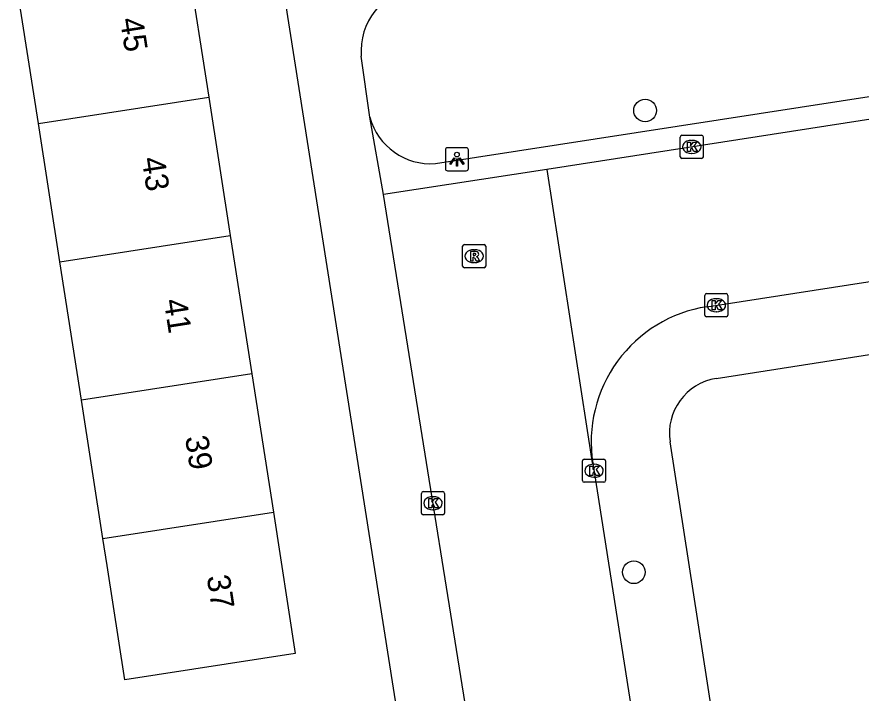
# Model space of a CAD drawing. Extents: x 160077 to 160945, y 386481 to 387498.
# Drawn here: x 160327.89 to 160364.4, y 387381.1 to 387410.32 of the extents above; entities that cross this region are included whole.
import ezdxf

# ---------------------------------------------------------------- set-up
doc = ezdxf.new("R2010")
doc.units = 0
for name, color, linetype in [('IMGEO_Boom', 7, 'Continuous'), ('IMGEO_Kolk', 7, 'Continuous'), ('IMGEO_Lichtpunt', 7, 'Continuous'), ('IMGEO_Pand', 7, 'Continuous'), ('IMGEO_Pand_nummerreeks', 7, 'Continuous'), ('IMGEO_Rijbaan_lokaal_open', 7, 'Continuous'), ('IMGEO_Rioolput', 7, 'Continuous'), ('IMGEO_Voetpad_open', 7, 'Continuous')]:
    doc.layers.add(name, color=color, linetype=linetype)

msp = doc.modelspace()

# ---------------------------------------------------------------- linework, layer by layer
at = {"layer": 'IMGEO_Boom'}
for centre in [(160355.058, 387406.272), (160354.57, 387386.318)]:
    msp.add_circle(centre, 0.489, dxfattribs=at)
at = {"layer": 'IMGEO_Kolk'}
for p, q in [((160356.576, 387404.276), (160356.576, 387405.128)), ((160356.651, 387405.202), (160357.503, 387405.202)), ((160357.577, 387405.128), (160357.577, 387404.276)), ((160357.064, 387404.982), (160357.089, 387404.982)), ((160357.087, 387404.422), (160357.062, 387404.422)), ((160357.503, 387404.202), (160356.651, 387404.202)), ((160357.64, 387397.432), (160357.64, 387398.284)), ((160357.715, 387398.358), (160358.567, 387398.358)), ((160358.641, 387398.284), (160358.641, 387397.432)), ((160358.128, 387398.138), (160358.153, 387398.138)), ((160358.151, 387397.578), (160358.126, 387397.578)), ((160358.567, 387397.358), (160357.715, 387397.358)), ((160352.35, 387390.279), (160352.35, 387391.131)), ((160352.425, 387391.205), (160353.277, 387391.205)), ((160352.838, 387390.985), (160352.863, 387390.985)), ((160353.351, 387391.131), (160353.351, 387390.279)), ((160353.277, 387390.205), (160352.425, 387390.205)), ((160352.861, 387390.425), (160352.836, 387390.425)), ((160345.463, 387389.801), (160346.315, 387389.801)), ((160345.388, 387388.875), (160345.388, 387389.727)), ((160345.876, 387389.581), (160345.901, 387389.581)), ((160346.389, 387389.727), (160346.389, 387388.875)), ((160346.315, 387388.801), (160345.463, 387388.801)), ((160345.899, 387389.021), (160345.874, 387389.021))]:
    msp.add_line(p, q, dxfattribs=at)
for points in [[(160356.576, 387404.276), (160356.576, 387405.128)], [(160356.651, 387405.202), (160357.503, 387405.202)], [(160357.577, 387405.128), (160357.577, 387404.276)], [(160356.897, 387404.902), (160357.02, 387404.902), (160357.02, 387404.751), (160357.15, 387404.902), (160357.314, 387404.902), (160357.168, 387404.751), (160357.321, 387404.502), (160357.169, 387404.502), (160357.084, 387404.666), (160357.02, 387404.599), (160357.02, 387404.502), (160356.897, 387404.502), (160356.897, 387404.902)], [(160357.503, 387404.202), (160356.651, 387404.202)], [(160357.64, 387397.432), (160357.64, 387398.284)], [(160357.715, 387398.358), (160358.567, 387398.358)], [(160358.641, 387398.284), (160358.641, 387397.432)], [(160357.961, 387398.058), (160358.084, 387398.058), (160358.084, 387397.907), (160358.214, 387398.058), (160358.378, 387398.058), (160358.232, 387397.907), (160358.385, 387397.658), (160358.233, 387397.658), (160358.148, 387397.822), (160358.084, 387397.755), (160358.084, 387397.658), (160357.961, 387397.658), (160357.961, 387398.058)], [(160358.567, 387397.358), (160357.715, 387397.358)], [(160352.35, 387390.279), (160352.35, 387391.131)], [(160352.425, 387391.205), (160353.277, 387391.205)], [(160352.671, 387390.905), (160352.794, 387390.905), (160352.794, 387390.754), (160352.924, 387390.905), (160353.088, 387390.905), (160352.942, 387390.754), (160353.095, 387390.505), (160352.943, 387390.505), (160352.858, 387390.669), (160352.794, 387390.602), (160352.794, 387390.505), (160352.671, 387390.505), (160352.671, 387390.905)], [(160353.351, 387391.131), (160353.351, 387390.279)], [(160353.277, 387390.205), (160352.425, 387390.205)], [(160345.463, 387389.801), (160346.315, 387389.801)], [(160345.388, 387388.875), (160345.388, 387389.727)], [(160345.709, 387389.501), (160345.832, 387389.501), (160345.832, 387389.35), (160345.962, 387389.501), (160346.126, 387389.501), (160345.98, 387389.35), (160346.133, 387389.101), (160345.981, 387389.101), (160345.896, 387389.265), (160345.832, 387389.198), (160345.832, 387389.101), (160345.709, 387389.101), (160345.709, 387389.501)], [(160346.389, 387389.727), (160346.389, 387388.875)], [(160346.315, 387388.801), (160345.463, 387388.801)]]:
    msp.add_lwpolyline(points, dxfattribs=at)
for centre, start, end in [((160356.653, 387405.126), 91.552, 178.448), ((160356.653, 387405.126), 91.552, 178.448), ((160357.501, 387405.126), 1.552, 88.448), ((160357.501, 387405.126), 1.552, 88.448), ((160356.653, 387404.278), 181.552, 268.448), ((160356.653, 387404.278), 181.552, 268.448), ((160357.501, 387404.278), 271.552, 358.448), ((160357.501, 387404.278), 271.552, 358.448), ((160357.717, 387398.282), 91.552, 178.448), ((160357.717, 387398.282), 91.552, 178.448), ((160358.565, 387398.282), 1.552, 88.448), ((160358.565, 387398.282), 1.552, 88.448), ((160357.717, 387397.434), 181.552, 268.448), ((160357.717, 387397.434), 181.552, 268.448), ((160358.565, 387397.434), 271.552, 358.448), ((160358.565, 387397.434), 271.552, 358.448), ((160352.427, 387391.129), 91.552, 178.448), ((160352.427, 387391.129), 91.552, 178.448), ((160353.275, 387391.129), 1.552, 88.448), ((160353.275, 387391.129), 1.552, 88.448), ((160352.427, 387390.281), 181.552, 268.448), ((160352.427, 387390.281), 181.552, 268.448), ((160353.275, 387390.281), 271.552, 358.448), ((160353.275, 387390.281), 271.552, 358.448), ((160345.465, 387389.725), 91.552, 178.448), ((160345.465, 387389.725), 91.552, 178.448), ((160346.313, 387389.725), 1.552, 88.448), ((160346.313, 387389.725), 1.552, 88.448), ((160345.465, 387388.877), 181.552, 268.448), ((160345.465, 387388.877), 181.552, 268.448), ((160346.313, 387388.877), 271.552, 358.448), ((160346.313, 387388.877), 271.552, 358.448)]:
    msp.add_arc(centre, 0.0765, start, end, dxfattribs=at)
for centre, major_axis, ratio, start_param, end_param in [((160357.063, 387404.702), (-0.387, 0.002), 0.722429, 4.712389, 7.853982), ((160357.088, 387404.702), (-0.39, 0.002), 0.717154, 1.570796, 4.712389), ((160358.127, 387397.858), (-0.387, 0.002), 0.722429, 4.712389, 7.853982), ((160358.152, 387397.858), (-0.39, 0.002), 0.717154, 1.570796, 4.712389), ((160352.837, 387390.705), (-0.387, 0.002), 0.722429, 4.712389, 7.853982), ((160352.862, 387390.705), (-0.39, 0.002), 0.717154, 1.570796, 4.712389), ((160345.875, 387389.301), (-0.387, 0.002), 0.722429, 4.712389, 7.853982), ((160345.9, 387389.301), (-0.39, 0.002), 0.717154, 1.570796, 4.712389)]:
    msp.add_ellipse(centre, major_axis=major_axis, ratio=ratio, start_param=start_param, end_param=end_param, dxfattribs=at)
at = {"layer": 'IMGEO_Lichtpunt'}
for p, q in [((160346.422, 387404.571), (160346.422, 387403.764)), ((160346.422, 387404.571), (160346.422, 387403.764)), ((160347.324, 387404.666), (160346.516, 387404.666)), ((160347.324, 387404.666), (160346.516, 387404.666)), ((160347.418, 387403.764), (160347.418, 387404.571)), ((160347.418, 387403.764), (160347.418, 387404.571)), ((160346.516, 387403.67), (160347.324, 387403.67)), ((160346.516, 387403.67), (160347.324, 387403.67))]:
    msp.add_line(p, q, dxfattribs=at)
for points in [[(160346.796, 387404.235), (160346.835, 387404.207), (160346.647, 387403.945), (160346.609, 387403.972), (160346.796, 387404.235)], [(160346.898, 387404.187), (160346.945, 387404.187), (160346.945, 387403.865), (160346.898, 387403.865), (160346.898, 387404.187)], [(160347.008, 387404.207), (160347.046, 387404.234), (160347.233, 387403.972), (160347.194, 387403.944), (160347.008, 387404.207)]]:
    msp.add_lwpolyline(points, dxfattribs=at)
msp.add_circle((160346.921, 387404.369), 0.0994, dxfattribs=at)
for centre, start, end in [((160346.516, 387404.571), 90, 180), ((160346.516, 387404.571), 90, 180), ((160347.324, 387404.571), 0, 90), ((160347.324, 387404.571), 0, 90), ((160346.516, 387403.764), 180, 270), ((160346.516, 387403.764), 180, 270), ((160347.324, 387403.764), 270, 0), ((160347.324, 387403.764), 270, 360)]:
    msp.add_arc(centre, 0.0946, start, end, dxfattribs=at)
at = {"layer": 'IMGEO_Pand'}
for points in [[(160335.263, 387412.83), (160336.194, 387406.852)], [(160328.826, 387405.705), (160327.895, 387411.683)], [(160328.826, 387405.705), (160336.194, 387406.852)], [(160336.194, 387406.852), (160337.124, 387400.875)], [(160329.756, 387399.728), (160328.826, 387405.705)], [(160329.756, 387399.728), (160337.124, 387400.875)], [(160337.124, 387400.875), (160338.054, 387394.897)], [(160330.686, 387393.75), (160329.756, 387399.728)], [(160338.054, 387394.897), (160330.686, 387393.75)], [(160338.054, 387394.897), (160338.984, 387388.919)], [(160331.616, 387387.772), (160330.686, 387393.75)], [(160338.984, 387388.919), (160339.935, 387382.811), (160332.567, 387381.664), (160331.798, 387386.605), (160331.616, 387387.772)], [(160331.616, 387387.772), (160338.984, 387388.919)]]:
    msp.add_lwpolyline(points, dxfattribs=at)
at = {"layer": 'IMGEO_Rijbaan_lokaal_open'}
for points in [[(160424.814, 387415.201), (160415.588, 387413.774), (160377.259, 387407.826), (160350.809, 387403.731)], [(160357.735, 387397.796), (160404.969, 387405.121), (160426.161, 387408.269)], [(160350.809, 387403.731), (160343.75, 387402.638)], [(160350.809, 387403.731), (160352.774, 387391.05), (160352.799, 387391.033)], [(160348.577, 387372.565), (160343.75, 387402.638)], [(160352.799, 387391.033), (160358.665, 387353.61), (160366.562, 387302.662), (160369.173, 387285.284)]]:
    msp.add_lwpolyline(points, dxfattribs=at)
msp.add_arc((160358.644, 387391.95), 5.916, 98.834, 188.9181, dxfattribs=at)
at = {"layer": 'IMGEO_Rioolput'}
for p, q in [((160347.169, 387399.553), (160347.169, 387400.405)), ((160347.244, 387400.479), (160348.096, 387400.479)), ((160348.17, 387400.405), (160348.17, 387399.553)), ((160347.657, 387400.259), (160347.682, 387400.259)), ((160347.68, 387399.699), (160347.655, 387399.699)), ((160348.096, 387399.479), (160347.244, 387399.479))]:
    msp.add_line(p, q, dxfattribs=at)
for points in [[(160347.169, 387399.553), (160347.169, 387400.405)], [(160347.244, 387400.479), (160348.096, 387400.479)], [(160348.17, 387400.405), (160348.17, 387399.553)], [(160347.758, 387400.177), (160347.506, 387400.179), (160347.506, 387399.779)], [(160347.684, 387400.098), (160347.63, 387400.098), (160347.63, 387400.017)], [(160347.63, 387400.017), (160347.682, 387400.017)], [(160347.506, 387399.779), (160347.63, 387399.779), (160347.63, 387399.941), (160347.641, 387399.941)], [(160347.688, 387399.912), (160347.759, 387399.779), (160347.899, 387399.779), (160347.834, 387399.905)], [(160348.096, 387399.479), (160347.244, 387399.479)]]:
    msp.add_lwpolyline(points, dxfattribs=at)
for centre, radius, start, end in [((160347.246, 387400.403), 0.0765, 91.552, 178.448), ((160347.246, 387400.403), 0.0765, 91.552, 178.448), ((160348.094, 387400.403), 0.0765, 1.552, 88.448), ((160348.094, 387400.403), 0.0765, 1.552, 88.448), ((160347.666, 387400.206), 0.19, 274.7715, 282.9687), ((160347.69, 387400.002), 0.0964, 77.0061, 93.1865), ((160347.704, 387400.059), 0.0378, 276.6634, 79.6772), ((160347.757, 387400.067), 0.109, 350.3612, 89.416), ((160347.755, 387400.067), 0.112, 277.5842, 350.9817), ((160347.64, 387399.888), 0.0533, 26.0293, 88.6989), ((160347.739, 387399.852), 0.108, 29.5134, 73.7905), ((160347.246, 387399.555), 0.0765, 181.552, 268.448), ((160347.246, 387399.555), 0.0765, 181.552, 268.448), ((160348.094, 387399.555), 0.0765, 271.552, 358.448), ((160348.094, 387399.555), 0.0765, 271.552, 358.448)]:
    msp.add_arc(centre, radius, start, end, dxfattribs=at)
for centre, major_axis, ratio, start_param, end_param in [((160347.656, 387399.979), (-0.387, 0.002), 0.722429, 4.712389, 7.853982), ((160347.681, 387399.979), (-0.39, 0.002), 0.717154, 1.570796, 4.712389)]:
    msp.add_ellipse(centre, major_axis=major_axis, ratio=ratio, start_param=start_param, end_param=end_param, dxfattribs=at)
at = {"layer": 'IMGEO_Voetpad_open'}
for points in [[(160345.993, 387403.98), (160372.216, 387408.027), (160371.063, 387415.499)], [(160339.073, 387413.649), (160344.769, 387377.466)], [(160343.156, 387405.981), (160342.785, 387408.615)], [(160343.75, 387402.638), (160343.156, 387405.981)], [(160358.135, 387394.694), (160426.75, 387405.419)], [(160358.965, 387373.701), (160356.137, 387391.954)]]:
    msp.add_lwpolyline(points, dxfattribs=at)
for centre, radius, start, end in [((160345.534, 387408.852), 2.759, 97.9311, 184.9189), ((160345.793, 387406.708), 2.735, 195.4137, 274.1939), ((160358.508, 387392.323), 2.4, 98.9498, 188.8514)]:
    msp.add_arc(centre, radius, start, end, dxfattribs=at)

# ---------------------------------------------------------------- texts
at = {"layer": 'IMGEO_Pand_nummerreeks'}
for s, p in [('45', (160332.35, 387410.221)), ('43', (160333.287, 387404.199)), ('41', (160334.242, 387398.067)), ('39', (160335.162, 387392.156)), ('37', (160336.099, 387386.134))]:
    msp.add_text(s, height=1, rotation=278.8459, dxfattribs=at).set_placement(p)

doc.saveas('drawing.dxf')
